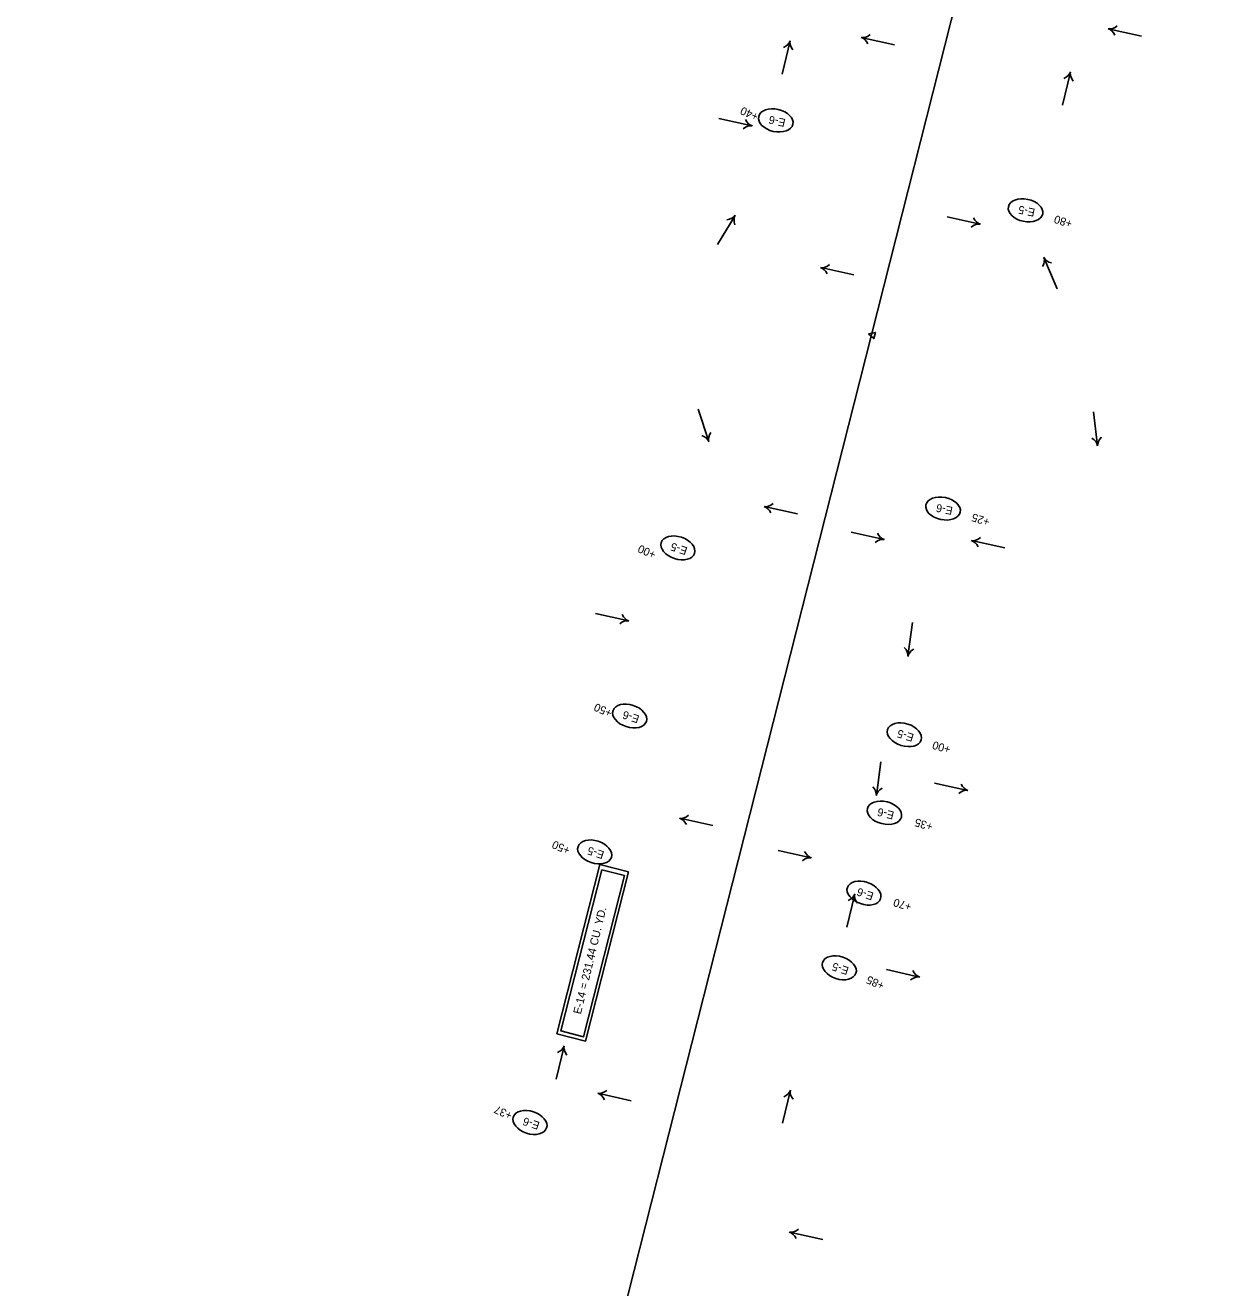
# Model space of a CAD drawing. Extents: x 669236 to 673912, y 735758 to 754788.
# Drawn here: x 669240 to 670180, y 737629 to 738615 of the extents above; entities that cross this region are included whole.
import ezdxf

# ---------------------------------------------------------------- set-up
doc = ezdxf.new("R2010")
doc.units = 0
for name, color, linetype in [('Default', 7, 'Continuous'), ('Prop_Horiz Alignment', 7, 'Continuous'), ('R_Erosion_3', 7, 'Continuous'), ('R_Flow Arrows', 7, 'Continuous')]:
    doc.layers.add(name, color=color, linetype=linetype)

msp = doc.modelspace()

# ---------------------------------------------------------------- linework, layer by layer
at = {"layer": 'Default'}
for p, q in [((669901.33, 738373), (670179.59, 739470.12)), ((669240.37, 735766.93), (669901.33, 738373))]:
    msp.add_line(p, q, dxfattribs=at)
at = {"layer": 'Prop_Horiz Alignment'}
msp.add_lwpolyline([(669898.91, 738373.62), (669904.37, 738374.81), (669903.14, 738369.96)], close=True, dxfattribs=at)
at = {"layer": 'R_Erosion_3'}
for points in [[(669711.58, 737953.51), (669678.02, 737821.27), (669655.61, 737826.96), (669689.18, 737959.2)], [(669708.44, 737950.5), (669676.51, 737824.69), (669658.82, 737829.18), (669690.75, 737954.99)]]:
    msp.add_lwpolyline(points, close=True, dxfattribs=at)
for centre, major_axis in [((669826.58, 738540.35), (-13.36, 3)), ((670021.64, 738470.12), (-13.41, 2.78)), ((669957.23, 738237.21), (-13.41, 2.78)), ((669750.14, 738206.46), (-13.02, 4.27)), ((669712.47, 738075.17), (-13.02, 4.27)), ((669927.02, 738060.54), (-13.07, 4.1)), ((669911.42, 737999.59), (-13.29, 3.31)), ((669685.13, 737969.02), (-13.02, 4.27)), ((669895.46, 737936.89), (-12.96, 4.43)), ((669876.21, 737878.5), (-13.02, 4.27)), ((669634.59, 737757.69), (-13.02, 4.27))]:
    msp.add_ellipse(centre, major_axis=major_axis, ratio=0.638788, dxfattribs=at)
at = {"layer": 'R_Flow Arrows'}
for p, q in [((670086.31, 738611.92), (670112.23, 738606.15)), ((669837.76, 738602.39), (669831.49, 738576.58)), ((669893.37, 738605.16), (669919.3, 738599.39)), ((670056.74, 738578.12), (670050.47, 738552.31)), ((669808.14, 738536.09), (669782.21, 738541.86)), ((669794.81, 738466.12), (669780.99, 738443.44)), ((669986.29, 738459.32), (669960.36, 738465.09)), ((669861.64, 738425.4), (669887.56, 738419.63)), ((670036.03, 738433.38), (670046.39, 738408.92)), ((669774.32, 738289.45), (669766.05, 738314.7)), ((670077.9, 738286.27), (670074.69, 738312.64)), ((669817.55, 738238.75), (669843.48, 738232.98)), ((669911.26, 738212.94), (669885.33, 738218.71)), ((669979.45, 738212.18), (670005.38, 738206.41)), ((669711.7, 738149.51), (669685.77, 738155.28)), ((669929.81, 738121.87), (669933.41, 738148.18)), ((669905.13, 738013.19), (669908.73, 738039.5)), ((669976.53, 738017.05), (669950.6, 738022.82)), ((669751.54, 737995.3), (669777.47, 737989.53)), ((669854.33, 737964.43), (669828.4, 737970.2)), ((669888.22, 737936.05), (669881.96, 737910.23)), ((669938.87, 737871.3), (669912.94, 737877.07)), ((669661.24, 737817.36), (669654.97, 737791.54)), ((669687.64, 737780.47), (669713.57, 737774.7)), ((669837.98, 737782.85), (669831.72, 737757.04)), ((669837.27, 737672), (669863.2, 737666.23))]:
    msp.add_line(p, q, dxfattribs=at)
for centre, major_axis, start_param, end_param in [((670081.5, 738592.34), (4.38, 19.68), 5.662936, 6.259934), ((670090.43, 738631.66), (-4.38, -19.68), 0.023252, 0.620249), ((669818.27, 738607.57), (19.59, -4.76), 5.662936, 6.259934), ((669857.41, 738597.89), (-19.59, 4.76), 0.023252, 0.620249), ((669888.56, 738585.58), (4.38, 19.68), 5.662936, 6.259934), ((669897.49, 738624.89), (-4.38, -19.68), 0.023252, 0.620249), ((670037.26, 738583.3), (19.59, -4.76), 5.662936, 6.259934), ((670076.39, 738573.62), (-19.59, 4.76), 0.023252, 0.620249), ((669804.02, 738516.36), (4.38, 19.68), 0.023252, 0.620249), ((669812.95, 738555.67), (-4.38, -19.68), 5.662936, 6.259934), ((669777.82, 738476.99), (17.22, -10.49), 5.662936, 6.259934), ((669812.16, 738455.86), (-17.22, 10.49), 0.023252, 0.620249), ((669991.09, 738478.9), (-4.38, -19.68), 5.662936, 6.259934), ((669982.16, 738439.59), (4.38, 19.68), 0.023252, 0.620249), ((669856.83, 738405.82), (4.38, 19.68), 5.662936, 6.259934), ((669865.76, 738445.13), (-4.38, -19.68), 0.023252, 0.620249), ((670017.3, 738425.92), (18.57, 7.86), 5.662936, 6.259934), ((670054.49, 738441.48), (-18.57, -7.86), 0.023252, 0.620249), ((669793.56, 738295.47), (-19.16, -6.27), 5.662936, 6.259934), ((669755.3, 738282.77), (19.16, 6.27), 0.023252, 0.620249), ((670057.92, 738283.58), (20.01, 2.43), 0.023252, 0.620249), ((670097.96, 738288.27), (-20.01, -2.43), 5.662936, 6.259934), ((669812.74, 738219.17), (4.38, 19.68), 5.662936, 6.259934), ((669821.67, 738258.48), (-4.38, -19.68), 0.023252, 0.620249), ((669916.07, 738232.52), (-4.38, -19.68), 5.662936, 6.259934), ((669907.14, 738193.21), (4.38, 19.68), 0.023252, 0.620249), ((669974.64, 738192.6), (4.38, 19.68), 5.662936, 6.259934), ((669983.57, 738231.91), (-4.38, -19.68), 0.023252, 0.620249), ((669707.57, 738129.78), (4.38, 19.68), 0.023252, 0.620249), ((669716.5, 738169.09), (-4.38, -19.68), 5.662936, 6.259934), ((669909.8, 738124.34), (19.98, -2.73), 0.023252, 0.620249), ((669949.72, 738118.7), (-19.98, 2.73), 5.662936, 6.259934), ((669885.13, 738015.66), (19.98, -2.73), 0.023252, 0.620249), ((669981.33, 738036.63), (-4.38, -19.68), 5.662936, 6.259934), ((669925.04, 738010.02), (-19.98, 2.73), 5.662936, 6.259934), ((669972.4, 737997.32), (4.38, 19.68), 0.023252, 0.620249), ((669746.73, 737975.72), (4.38, 19.68), 5.662936, 6.259934), ((669755.66, 738015.04), (-4.38, -19.68), 0.023252, 0.620249), ((669850.21, 737944.69), (4.38, 19.68), 0.023252, 0.620249), ((669859.13, 737984), (-4.38, -19.68), 5.662936, 6.259934), ((669868.74, 737941.23), (19.59, -4.76), 5.662936, 6.259934), ((669907.87, 737931.55), (-19.59, 4.76), 0.023252, 0.620249), ((669934.75, 737851.56), (4.38, 19.68), 0.023252, 0.620249), ((669943.68, 737890.88), (-4.38, -19.68), 5.662936, 6.259934), ((669641.75, 737822.54), (19.59, -4.76), 5.662936, 6.259934), ((669680.89, 737812.86), (-19.59, 4.76), 0.023252, 0.620249), ((669818.5, 737788.03), (19.59, -4.76), 5.662936, 6.259934), ((669682.83, 737760.89), (4.38, 19.68), 5.662936, 6.259934), ((669691.76, 737800.2), (-4.38, -19.68), 0.023252, 0.620249), ((669857.63, 737778.35), (-19.59, 4.76), 0.023252, 0.620249), ((669832.46, 737652.42), (4.38, 19.68), 5.662936, 6.259934), ((669841.39, 737691.74), (-4.38, -19.68), 0.023252, 0.620249)]:
    msp.add_ellipse(centre, major_axis=major_axis, ratio=0.5625, start_param=start_param, end_param=end_param, dxfattribs=at)

# ---------------------------------------------------------------- texts
at = {"layer": 'R_Erosion_3'}
for s, height, rotation, p in [('+40', 6.25, 155.86613, (669813.63, 738545.47)), ('E-6', 6.25, 167.35021, (669834.61, 738541.28)), ('E-5', 6.25, 168.28076, (670029.49, 738471.21)), ('+80', 6.25, 162.30814, (670058.7, 738462.15)), ('E-6', 6.25, 168.28076, (669965.25, 738238.27)), ('+25', 6.25, 162.30814, (669994.3, 738229.24)), ('+00', 6.25, 155.86613, (669733.6, 738203.37)), ('E-5', 6.25, 161.83875, (669758.06, 738206.66)), ('+50', 6.25, 155.86613, (669699.32, 738079.63)), ('E-6', 6.25, 161.83875, (669720.55, 738075.32)), ('E-5', 6.25, 162.56684, (669934.94, 738060.85)), ('+00', 6.25, 163.09173, (669963.65, 738051.59)), ('E-6', 6.25, 166.01245, (669919.47, 738000.33)), ('+35', 6.25, 163.09173, (669949.8, 737991.26)), ('+50', 6.25, 155.86613, (669666.56, 737972.33)), ('E-5', 6.25, 161.83875, (669693.05, 737969.23)), ('E-6', 6.25, 161.12034, (669903.55, 737936.94)), ('+70', 6.25, 163.09173, (669933.17, 737928.71)), ('E-14 = 231.44 CU. YD.', 6.2497, 76.50059, (669674.34, 737841.86)), ('E-5', 6.25, 161.83875, (669884.13, 737878.7)), ('+85', 6.25, 155.86613, (669912.05, 737866.75)), ('+37', 6.25, 155.86613, (669621.36, 737765.34)), ('E-6', 6.25, 161.83875, (669642.67, 737757.84))]:
    msp.add_text(s, height=height, rotation=rotation, dxfattribs=at).set_placement(p)

doc.saveas('drawing.dxf')
